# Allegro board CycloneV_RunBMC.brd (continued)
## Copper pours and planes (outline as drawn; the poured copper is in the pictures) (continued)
VR_P2V5_AUX_FB on BOTTOM: 3.83,18.73 5.33,18.73 5.58,18.47 5.58,17.23 5.45,17.1 5.05,17.1 4.95,17.2 4.95,17.68 4.44,17.68 4.36,17.61 3.68,17.61 3.55,17.73 3.55,18.45

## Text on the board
Ref Des/Silkscreen Top: TRACE32 | AA | DEDIPROG | BB | DEBUG | JTAG | Inte1 SSMC RUNBMC | PBA# K72990-100 | POC
